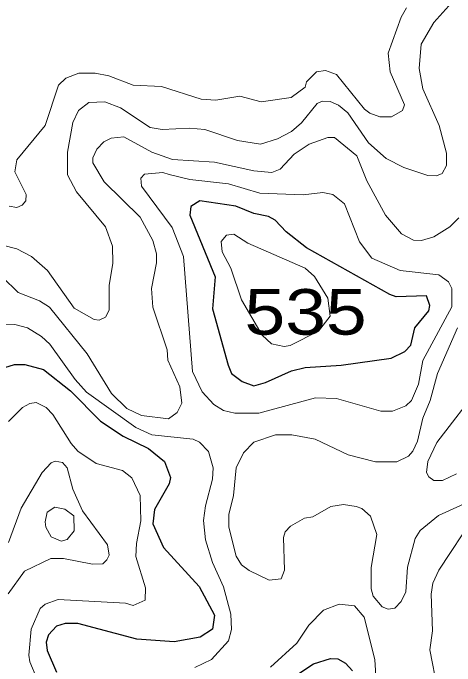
# Model space of a CAD drawing. Extents: x 577 to 602.9, y 7483.8 to 7511.6.
# Drawn here: x 591.855 to 592.63, y 7487.785 to 7488.932 of the extents above; entities that cross this region are included whole.
import ezdxf
from ezdxf.enums import TextEntityAlignment as Align

# ---------------------------------------------------------------- set-up
doc = ezdxf.new("R2010")
doc.units = 0
doc.header["$LTSCALE"] = 0.032
doc.layers.add('1', color=7, linetype='Continuous', lineweight=25)
doc.layers.add('2', color=7, linetype='Continuous', lineweight=13)
doc.layers.add('61', color=7, linetype='Continuous')

msp = doc.modelspace()

# ---------------------------------------------------------------- linework, layer by layer
at = {"layer": '1'}
msp.add_lwpolyline([(592.2976, 7488.283), (592.3432, 7488.3035), (592.367, 7488.3099), (592.4306, 7488.3139), (592.5181, 7488.3258), (592.542, 7488.3377), (592.5523, 7488.3489), (592.5595, 7488.3791), (592.5841, 7488.4093), (592.5857, 7488.4188), (592.5801, 7488.4355), (592.5269, 7488.4339), (592.5157, 7488.4379), (592.3694, 7488.5198), (592.3336, 7488.5476), (592.3146, 7488.5683), (592.3026, 7488.5747), (592.2772, 7488.5803), (592.2454, 7488.593), (592.1826, 7488.6025), (592.1666, 7488.5922), (592.1651, 7488.5771), (592.2096, 7488.4689), (592.2048, 7488.4125), (592.2319, 7488.3139), (592.2382, 7488.2988), (592.2565, 7488.2852), (592.2772, 7488.2773)], close=True, dxfattribs=at)
for points in [[(591.8406, 7488.3099), (591.8573, 7488.3147), (591.8756, 7488.3147), (591.9082, 7488.3059), (591.9559, 7488.2685), (592.0084, 7488.2153), (592.0482, 7488.189), (592.0927, 7488.1676), (592.1205, 7488.1445), (592.1309, 7488.1167), (592.1285, 7488.1055), (592.103, 7488.0602), (592.0999, 7488.0348), (592.1189, 7487.9934), (592.181, 7487.925), (592.208, 7487.8749), (592.2048, 7487.8503), (592.1833, 7487.836), (592.1372, 7487.828), (592.072, 7487.8328), (591.9686, 7487.8598), (591.9464, 7487.8598), (591.9313, 7487.8551), (591.917, 7487.8399), (591.913, 7487.8272), (591.9146, 7487.8129), (591.9313, 7487.7747)], [(592.3456, 7487.7652), (592.3821, 7487.7891), (592.4116, 7487.7986), (592.4243, 7487.7978), (592.4378, 7487.7906), (592.4505, 7487.7771)]]:
    msp.add_lwpolyline(points, dxfattribs=at)
at = {"layer": '2'}
for points in [[(591.8366, 7488.5246), (591.8613, 7488.5182), (591.8875, 7488.5047), (591.9154, 7488.4801), (591.9623, 7488.4141), (591.9973, 7488.3942), (592.006, 7488.3926), (592.0172, 7488.3982), (592.0235, 7488.4101), (592.0235, 7488.4538), (592.0299, 7488.4928), (592.0291, 7488.523), (592.0172, 7488.5564), (591.9663, 7488.6184), (591.9504, 7488.6478), (591.9504, 7488.6876), (591.9599, 7488.7401), (591.9694, 7488.7608), (591.9877, 7488.7751), (592.0156, 7488.7759), (592.0434, 7488.7655), (592.0951, 7488.7313), (592.1166, 7488.7274), (592.1643, 7488.7297), (592.1913, 7488.7274), (592.2486, 7488.7083), (592.2891, 7488.7019), (592.3185, 7488.7115), (592.3432, 7488.7242), (592.3607, 7488.7393), (592.3885, 7488.7735), (592.3972, 7488.7775), (592.4108, 7488.7767), (592.4259, 7488.7703), (592.4418, 7488.7568), (592.4784, 7488.7043), (592.5094, 7488.6765), (592.5404, 7488.6606), (592.5825, 7488.647), (592.5976, 7488.6463), (592.6072, 7488.6502), (592.6151, 7488.6645), (592.6151, 7488.686), (592.6024, 7488.7345), (592.5738, 7488.7989), (592.5674, 7488.8347), (592.5706, 7488.8776), (592.5929, 7488.9158), (592.6247, 7488.9508)], [(591.8478, 7488.593), (591.8613, 7488.5906), (591.8708, 7488.5946), (591.8772, 7488.6025), (591.878, 7488.6136), (591.8581, 7488.6534), (591.8613, 7488.6741), (591.9114, 7488.7345), (591.9345, 7488.8053), (591.9472, 7488.818), (591.9702, 7488.8268), (591.9989, 7488.8268), (592.0227, 7488.822), (592.0657, 7488.8053), (592.115, 7488.8029), (592.1849, 7488.7806), (592.2104, 7488.779), (592.2525, 7488.7862), (592.2899, 7488.7759), (592.3424, 7488.7838), (592.367, 7488.8021), (592.3694, 7488.8116), (592.3869, 7488.8291), (592.4028, 7488.8315), (592.4219, 7488.8244), (592.4712, 7488.7631), (592.4807, 7488.756), (592.4982, 7488.7496), (592.5189, 7488.7496), (592.538, 7488.7608), (592.5412, 7488.7711), (592.5165, 7488.8291), (592.5125, 7488.8617), (592.5356, 7488.9246), (592.5452, 7488.9413)], [(592.6366, 7488.5723), (592.6207, 7488.5564), (592.5929, 7488.5389), (592.5714, 7488.5325), (592.5571, 7488.5333), (592.5364, 7488.5445), (592.5078, 7488.5771), (592.4752, 7488.6375), (592.4577, 7488.6812), (592.4187, 7488.7138), (592.4068, 7488.7138), (592.3742, 7488.7019), (592.3479, 7488.6844), (592.3233, 7488.6582), (592.309, 7488.6518), (592.2772, 7488.655), (592.208, 7488.6701), (592.1348, 7488.6749), (592.0983, 7488.6876), (592.049, 7488.7146), (592.0267, 7488.7123), (592.014, 7488.7059), (592.002, 7488.6932), (591.9949, 7488.6781), (591.9949, 7488.6693), (592.0148, 7488.6359), (592.0776, 7488.5739), (592.0999, 7488.5325), (592.1062, 7488.5095), (592.1062, 7488.4936), (592.0975, 7488.4483), (592.0999, 7488.4156), (592.1253, 7488.3409), (592.1261, 7488.3226), (592.1476, 7488.2757), (592.1507, 7488.2471), (592.1428, 7488.2304), (592.1277, 7488.2192), (592.08, 7488.2256), (592.0545, 7488.2375), (592.0275, 7488.2638), (591.9846, 7488.3337), (591.9186, 7488.4156), (591.9011, 7488.4268), (591.8637, 7488.4411), (591.8366, 7488.4681)], [(591.8255, 7488.3846), (591.8581, 7488.3854), (591.8804, 7488.3791), (591.905, 7488.364), (591.9193, 7488.3504), (591.9639, 7488.2884), (591.9838, 7488.2662), (592.0704, 7488.2041), (592.0983, 7488.1914), (592.1706, 7488.1835), (592.1818, 7488.1787), (592.1977, 7488.162), (592.2056, 7488.1334), (592.2048, 7488.1135), (592.1921, 7488.0666), (592.1889, 7488.0411), (592.1921, 7488.0069), (592.2048, 7487.9672), (592.2239, 7487.9242), (592.2366, 7487.8765), (592.2382, 7487.8495), (592.2326, 7487.8296), (592.2032, 7487.797), (592.1738, 7487.7827)], [(592.6525, 7488.0729), (592.6008, 7488.0499), (592.569, 7488.0236), (592.5603, 7488.0093), (592.5467, 7487.9592), (592.5436, 7487.9155), (592.5356, 7487.8988), (592.5245, 7487.8869), (592.5125, 7487.8853), (592.5022, 7487.8892), (592.4863, 7487.9083), (592.4831, 7487.9211), (592.4831, 7487.9584), (592.4927, 7488.0165), (592.4815, 7488.0483), (592.4664, 7488.0618), (592.4569, 7488.0658), (592.4346, 7488.069), (592.4124, 7488.0658), (592.3806, 7488.0475), (592.3662, 7488.0451), (592.3416, 7488.0308), (592.332, 7488.0212), (592.3289, 7488.0109), (592.3312, 7487.9537), (592.3249, 7487.9385), (592.3042, 7487.9362), (592.2692, 7487.9529), (592.2557, 7487.9632), (592.2462, 7487.9783), (592.2334, 7488.0292), (592.2334, 7488.0515), (592.2414, 7488.0849), (592.2462, 7488.1334), (592.2589, 7488.1596), (592.2772, 7488.1787), (592.3153, 7488.1914), (592.344, 7488.1914), (592.3845, 7488.1835), (592.4426, 7488.1564), (592.4903, 7488.1437), (592.5277, 7488.1437), (592.5483, 7488.154), (592.5563, 7488.1628), (592.5642, 7488.1803), (592.5738, 7488.2208), (592.5865, 7488.2518), (592.5992, 7488.2988), (592.6342, 7488.3791)], [(592.6748, 7488.2773), (592.5984, 7488.1779), (592.5825, 7488.1445), (592.5801, 7488.1254), (592.5841, 7488.1175), (592.5929, 7488.1111), (592.608, 7488.1111), (592.6326, 7488.123)], [(591.847, 7488.2145), (591.8716, 7488.2391), (591.8844, 7488.2463), (591.8955, 7488.2479), (591.913, 7488.2391), (591.9249, 7488.2272), (591.9567, 7488.1763), (591.9686, 7488.1628), (592.0005, 7488.1413), (592.0466, 7488.1286), (592.0633, 7488.1159), (592.0776, 7488.0849), (592.0792, 7488.0403), (592.0712, 7488.0006), (592.0704, 7487.9775), (592.0871, 7487.9226), (592.0863, 7487.9012), (592.0657, 7487.8916), (592.0521, 7487.8956), (591.9337, 7487.902), (591.9114, 7487.894), (591.9026, 7487.8861), (591.8867, 7487.8503), (591.8828, 7487.8042), (591.8844, 7487.793), (591.909, 7487.7342)], [(591.847, 7488.0022), (591.8693, 7488.0626), (591.9058, 7488.1254), (591.9217, 7488.1421), (591.9289, 7488.1453), (591.9416, 7488.1429), (591.9496, 7488.1334), (591.9599, 7488.096), (591.9766, 7488.0578), (592.0203, 7487.9982), (592.0235, 7487.9799), (592.0195, 7487.9719), (592.0124, 7487.9648), (591.9941, 7487.964), (591.9432, 7487.9743), (591.9209, 7487.9743), (591.8748, 7487.9521), (591.8462, 7487.9123)], [(592.5992, 7487.7445), (592.5857, 7487.8137), (592.5905, 7487.8471), (592.5881, 7487.9115), (592.5913, 7487.9306), (592.6016, 7487.9537), (592.6644, 7488.0483)], [(592.3066, 7487.7835), (592.3527, 7487.8256), (592.3734, 7487.8574), (592.3996, 7487.8837), (592.4267, 7487.894), (592.4537, 7487.8908), (592.4704, 7487.871), (592.4895, 7487.797), (592.4927, 7487.7398)]]:
    msp.add_lwpolyline(points, dxfattribs=at)
for points in [[(592.1285, 7488.6486), (592.1651, 7488.6399), (592.2326, 7488.6319), (592.2875, 7488.616), (592.3639, 7488.6129), (592.398, 7488.6168), (592.4155, 7488.6136), (592.4362, 7488.5969), (592.4625, 7488.5302), (592.4839, 7488.5015), (592.534, 7488.4801), (592.6016, 7488.4721), (592.6183, 7488.4602), (592.6247, 7488.4483), (592.6247, 7488.4164), (592.5738, 7488.3218), (592.5658, 7488.2805), (592.5539, 7488.2518), (592.5436, 7488.2423), (592.5205, 7488.2328), (592.4998, 7488.2328), (592.4219, 7488.255), (592.3853, 7488.2566), (592.2859, 7488.2296), (592.2438, 7488.2296), (592.2239, 7488.2343), (592.2072, 7488.2447), (592.1865, 7488.267), (592.1698, 7488.3027), (592.1539, 7488.5047), (592.134, 7488.5556), (592.08, 7488.628), (592.0792, 7488.6423), (592.0855, 7488.6494), (592.1173, 7488.6518)], [(592.4068, 7488.4316), (592.3837, 7488.4697), (592.367, 7488.484), (592.2668, 7488.5278), (592.2422, 7488.5437), (592.2295, 7488.5421), (592.2199, 7488.531), (592.2215, 7488.5127), (592.2366, 7488.484), (592.2557, 7488.4284), (592.2915, 7488.3663), (592.3082, 7488.3512), (592.3305, 7488.3465), (592.3408, 7488.3481), (592.3904, 7488.3737), (592.4108, 7488.3997)], [(591.9114, 7488.0387), (591.9122, 7488.0292), (591.9217, 7488.0125), (591.9392, 7488.0045), (591.9496, 7488.0077), (591.9623, 7488.0228), (591.9615, 7488.0491), (591.9456, 7488.061), (591.9281, 7488.0642), (591.9146, 7488.0554)]]:
    msp.add_lwpolyline(points, close=True, dxfattribs=at)

# ---------------------------------------------------------------- texts
at = {"layer": '61', "width": 1.2}
msp.add_text('535', height=0.08, dxfattribs=at).set_placement((592.3679, 7488.3673), align=Align.CENTER)

doc.saveas('drawing.dxf')
